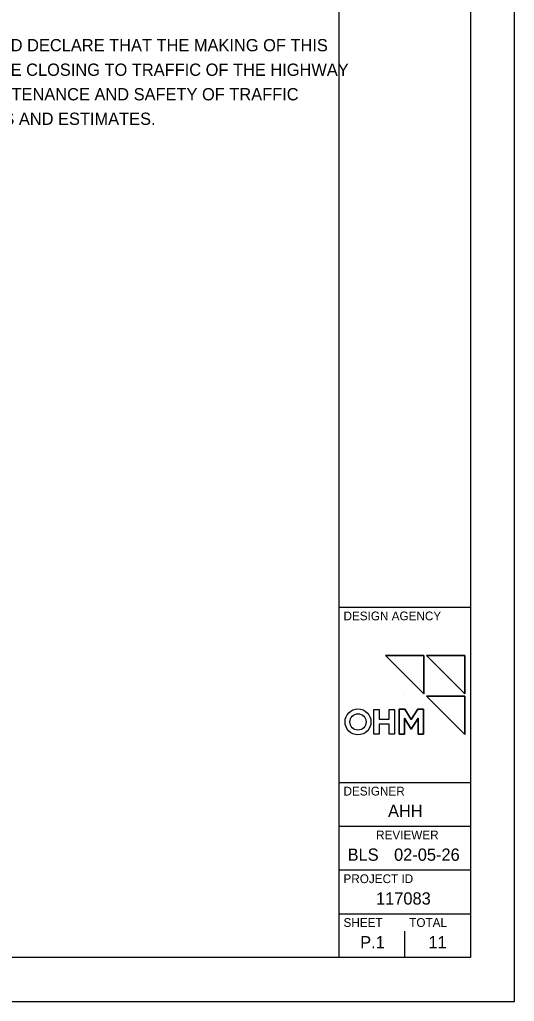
# Model space of a CAD drawing. Extents: x 0 to 34, y 0 to 22.
# Drawn here: x 28.35 to 34, y 0 to 11.21 of the extents above; entities that cross this region are included whole.
import ezdxf

# ---------------------------------------------------------------- set-up
doc = ezdxf.new("R2010")
doc.units = 0
for name, color, linetype in [('Default', 7, 'Continuous'), ('SH_Border', 7, 'Continuous'), ('SH_Cut_Line', 7, 'Continuous'), ('SH_Data', 7, 'Continuous'), ('TX_P_Misc', 7, 'Continuous')]:
    doc.layers.add(name, color=color, linetype=linetype)

msp = doc.modelspace()

# ---------------------------------------------------------------- linework, layer by layer
at = {"layer": 'Default'}
for points in [[(32.966, 3.948), (32.966, 3.51), (32.53, 3.948)], [(33.433, 3.948), (33.433, 3.51), (32.997, 3.948)], [(33.433, 3.483), (33.433, 3.045), (32.997, 3.483)], [(32.397, 3.333), (32.457, 3.333), (32.457, 3.22), (32.571, 3.22), (32.571, 3.333), (32.631, 3.333), (32.631, 3.052), (32.571, 3.052), (32.571, 3.166), (32.457, 3.166), (32.457, 3.052), (32.397, 3.052)], [(32.9, 3.335), (32.963, 3.335), (32.963, 3.052), (32.903, 3.052), (32.903, 3.233), (32.824, 3.108), (32.745, 3.233), (32.745, 3.052), (32.685, 3.052), (32.685, 3.335), (32.748, 3.335), (32.824, 3.216)]]:
    msp.add_lwpolyline(points, close=True, dxfattribs=at)
at = {"layer": 'SH_Border'}
for p, q in [((32, 0.5), (32, 21.5)), ((32, 4.5), (33.5, 4.5)), ((32, 2.5), (33.5, 2.5)), ((32, 2), (33.5, 2)), ((32, 1.5), (33.5, 1.5)), ((32, 1), (33.5, 1))]:
    msp.add_line(p, q, dxfattribs=at)
msp.add_lwpolyline([(1.5, 21.5), (33.5, 21.5), (33.5, 0.5), (1.5, 0.5)], close=True, dxfattribs=at)
at = {"layer": 'SH_Cut_Line'}
msp.add_lwpolyline([(0, 0), (34, 0), (34, 22), (0, 22)], close=True, dxfattribs=at)
at = {"layer": 'SH_Data'}
for p, q in [((32.75, 3.5), (32.75, 3.5)), ((32.75, 0.5), (32.75, 0.8)), ((32.375, 0.675), (32.375, 0.675))]:
    msp.add_line(p, q, dxfattribs=at)
at = {"layer": 'TX_P_Misc'}
for p, q in [((32.745, 3.052), (32.745, 3.233)), ((32.745, 3.233), (32.824, 3.108)), ((32.824, 3.108), (32.903, 3.233)), ((32.903, 3.233), (32.903, 3.052))]:
    msp.add_line(p, q, dxfattribs=at)
for points in [[(32.53, 3.948), (32.966, 3.51), (32.966, 3.948), (32.53, 3.948)], [(32.997, 3.948), (33.433, 3.51), (33.433, 3.948), (32.997, 3.948)], [(32.997, 3.483), (33.433, 3.045), (33.433, 3.483), (32.997, 3.483)], [(32.824, 3.216), (32.748, 3.335), (32.685, 3.335), (32.685, 3.052), (32.745, 3.052)], [(32.903, 3.052), (32.963, 3.052), (32.963, 3.335), (32.9, 3.335), (32.824, 3.216)]]:
    msp.add_lwpolyline(points, dxfattribs=at)
msp.add_lwpolyline([(32.397, 3.333), (32.457, 3.333), (32.457, 3.22), (32.571, 3.22), (32.571, 3.333), (32.631, 3.333), (32.631, 3.052), (32.571, 3.052), (32.571, 3.166), (32.457, 3.166), (32.457, 3.052), (32.397, 3.052)], close=True, dxfattribs=at)
for radius in [0.148, 0.148, 0.0927, 0.0927]:
    msp.add_circle((32.215, 3.19), radius, dxfattribs=at)

# ---------------------------------------------------------------- texts
at = {"layer": 'SH_Data'}
for s, height, p in [(' I HEREBY APPROVE THESE PLANS AND DECLARE THAT THE MAKING OF THIS', 0.14, (24.714, 10.846)), ('IMPROVEMENT WILL NOT REQUIRE THE CLOSING TO TRAFFIC OF THE HIGHWAY', 0.14, (24.714, 10.566)), ('AND THAT PROVISIONS FOR THE MAINTENANCE AND SAFETY OF TRAFFIC', 0.14, (24.714, 10.286)), ('WILL BE AS SET FORTH ON THE PLANS AND ESTIMATES.', 0.14, (24.714, 10.006)), ('DESIGN AGENCY', 0.1, (32.05, 4.35)), ('DESIGNER', 0.1, (32.05, 2.35)), ('AHH', 0.14, (32.558, 2.105)), ('REVIEWER', 0.1, (32.422, 1.85)), ('BLS', 0.14, (32.097, 1.605)), ('02-05-26', 0.14, (32.627, 1.605)), ('PROJECT ID', 0.1, (32.05, 1.35)), ('117083', 0.14, (32.421, 1.105)), ('SHEET', 0.1, (32.05, 0.85)), ('TOTAL', 0.1, (32.8, 0.85)), ('P.1', 0.14, (32.24, 0.605)), ('11', 0.14, (33.019, 0.605))]:
    msp.add_text(s, height=height, dxfattribs=at).set_placement(p)

doc.saveas('drawing.dxf')
